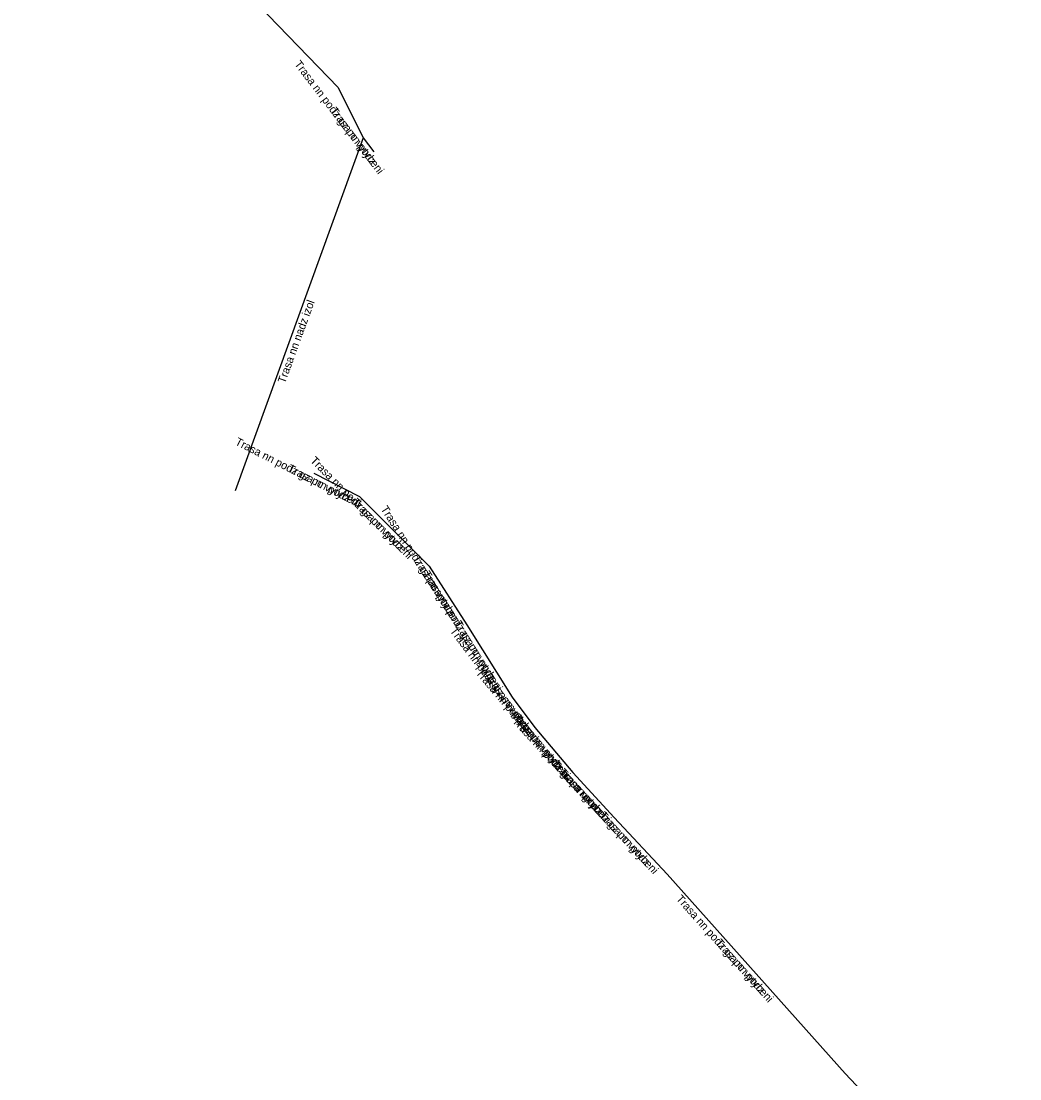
# Model space of a CAD drawing. Extents: x -666920 to -666608, y -1105526 to -1105233.
# Drawn here: x -666864.1 to -666801.7, y -1105447.2 to -1105381.1 of the extents above; entities that cross this region are included whole.
import ezdxf

# ---------------------------------------------------------------- set-up
doc = ezdxf.new("R2010")
doc.units = 0
doc.layers.add('Popiskový text - Ostatní atributy Trasy', color=7, linetype='Continuous')
doc.layers.add('Spojnice NN', color=7, linetype='Continuous')

msp = doc.modelspace()

# ---------------------------------------------------------------- linework, layer by layer
at = {"layer": 'Spojnice NN'}
for points in [[(-666862.73, -1105353.61), (-666863.87, -1105356.02), (-666864.09, -1105360.33), (-666864, -1105363.54), (-666862.51, -1105366.07), (-666856.69, -1105372.29), (-666851.79, -1105377.51), (-666844.29, -1105385.29), (-666842.72, -1105388.43)], [(-666842.72, -1105388.43), (-666850.72, -1105410.49)], [(-666842.72, -1105388.43), (-666842.049, -1105389.31)], [(-666842.72, -1105388.43), (-666842.049, -1105389.31)], [(-666845.81, -1105409.37), (-666842.95, -1105410.83)], [(-666845.81, -1105409.37), (-666842.95, -1105410.83)], [(-666842.95, -1105410.83), (-666838.59, -1105415.19)], [(-666842.95, -1105410.83), (-666838.59, -1105415.19)], [(-666838.59, -1105415.19), (-666836.25, -1105418.86)], [(-666838.59, -1105415.19), (-666836.25, -1105418.86)], [(-666836.25, -1105418.86), (-666833.41, -1105423.38)], [(-666836.25, -1105418.86), (-666833.41, -1105423.38)], [(-666833.41, -1105423.38), (-666832, -1105425.26)], [(-666833.41, -1105423.38), (-666832, -1105425.26)], [(-666832, -1105425.26), (-666829.62, -1105428.08)], [(-666832, -1105425.26), (-666829.62, -1105428.08)], [(-666829.62, -1105428.08), (-666827.03, -1105430.89)], [(-666829.62, -1105428.08), (-666827.03, -1105430.89)], [(-666827.03, -1105430.89), (-666823.73, -1105434.43)], [(-666827.03, -1105430.89), (-666823.73, -1105434.43)], [(-666823.73, -1105434.43), (-666812.6, -1105446.89)], [(-666823.73, -1105434.43), (-666812.6, -1105446.89)], [(-666812.6, -1105446.89), (-666801.69, -1105458.45)], [(-666812.6, -1105446.89), (-666801.69, -1105458.45)]]:
    msp.add_lwpolyline(points, dxfattribs=at)

# ---------------------------------------------------------------- texts
at = {"layer": 'Popiskový text - Ostatní atributy Trasy'}
for s, rotation, p in [('Trasa nn podz gz po vytyceni', 307.35152, (-666847.046, -1105383.832)), ('Trasa nn podz', 307.35152, (-666844.81, -1105386.762)), ('Trasa nn nadz izol', 70.06696, (-666847.606, -1105403.808)), ('Trasa nn podz gz po vytyceni', 332.95617, (-666850.761, -1105407.572)), ('Trasa nn podz gz po vytyceni', 315, (-666846.061, -1105408.638)), ('Trasa nn podz', 332.95617, (-666847.479, -1105409.248)), ('Trasa nn podz', 315, (-666843.455, -1105411.244)), ('Trasa nn podz gz po vytyceni', 302.52167, (-666841.641, -1105411.613)), ('Trasa nn podz', 302.52167, (-666839.66, -1105414.72)), ('Trasa nn podz gz po vytyceni', 302.14191, (-666839.016, -1105415.681)), ('Trasa nn podz gz po vytyceni', 306.8699, (-666837.325, -1105419.244)), ('Trasa nn podz', 302.14191, (-666837.055, -1105418.801)), ('Trasa nn podz gz po vytyceni', 310.16342, (-666835.714, -1105421.868)), ('Trasa nn podz', 306.8699, (-666835.114, -1105422.192)), ('Trasa nn podz gz po vytyceni', 312.66702, (-666833.434, -1105424.901)), ('Trasa nn podz', 310.16342, (-666833.337, -1105424.684)), ('Trasa nn podz', 312.66702, (-666830.936, -1105427.611)), ('Trasa nn podz gz po vytyceni', 312.99045, (-666830.515, -1105428.106)), ('Trasa nn podz', 312.99045, (-666828.002, -1105430.801)), ('Trasa nn podz gz po vytyceni', 311.77309, (-666823.201, -1105435.997)), ('Trasa nn podz', 311.77309, (-666820.746, -1105438.745))]:
    msp.add_text(s, height=0.5, rotation=rotation, dxfattribs=at).set_placement(p)

doc.saveas('drawing.dxf')
